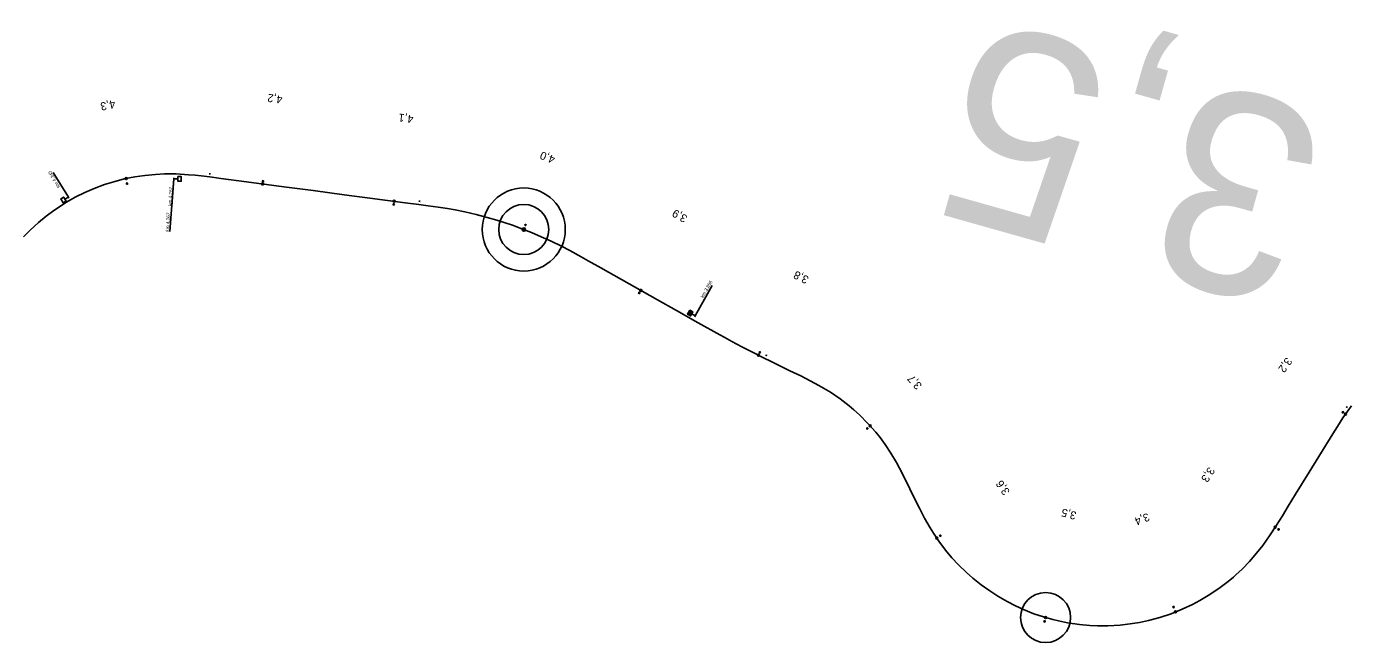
# Model space of a CAD drawing. Extents: x -738519 to -733269, y -1123734 to -1116309.
# Drawn here: x -737468 to -736475, y -1121770 to -1121307 of the extents above; entities that cross this region are included whole.
import ezdxf

# ---------------------------------------------------------------- set-up
doc = ezdxf.new("R2010")
doc.units = 0
doc.layers.add('Vrstva 1', color=7, linetype='Continuous')
doc.layers.add('Vrstva 7', color=7, linetype='Continuous')

msp = doc.modelspace()

# ---------------------------------------------------------------- linework, layer by layer
at = {"layer": 'Vrstva 1'}
for points in [[(-736980.55, -1121520.47), (-736994.79, -1121512.43), (-737006.13, -1121506.04), (-737037.15, -1121488.58), (-737041.66, -1121486.03), (-737045.03, -1121484.13), (-737051.95, -1121480.26), (-737060.41, -1121475.6), (-737066.65, -1121472.32), (-737074.48, -1121468.48), (-737081.82, -1121465.13), (-737089.05, -1121462.07), (-737096.43, -1121459.17), (-737103.49, -1121456.6), (-737109.72, -1121454.5), (-737115.02, -1121452.83), (-737122.31, -1121450.71), (-737130.59, -1121448.55), (-737139.15, -1121446.56), (-737146.38, -1121445.1), (-737152.14, -1121444.06), (-737159.1, -1121442.98), (-737166.62, -1121441.93), (-737173.49, -1121441.02), (-737183.78, -1121439.67), (-737210.21, -1121436.2), (-737229.58, -1121433.65), (-737252.71, -1121430.59), (-737274.7, -1121427.68), (-737302.82, -1121423.99), (-737322.07, -1121421.44), (-737328.44, -1121420.59), (-737334.37, -1121419.85), (-737341.18, -1121419.08), (-737346.17, -1121418.63), (-737355.36, -1121418.09), (-737364.19, -1121418.05), (-737371.06, -1121418.37), (-737378.94, -1121419.13), (-737386.42, -1121420.24), (-737394.37, -1121421.82), (-737402.27, -1121423.87), (-737409.27, -1121426.07), (-737416.85, -1121428.91), (-737423.86, -1121431.97), (-737430.65, -1121435.33), (-737438.05, -1121439.53), (-737442.95, -1121442.62), (-737447.09, -1121445.44), (-737453.01, -1121449.85), (-737458.73, -1121454.55), (-737464.94, -1121460.22), (-737469.92, -1121465.24)], [(-736980.55, -1121520.47), (-736994.79, -1121512.43), (-737006.13, -1121506.04), (-737037.15, -1121488.58), (-737041.66, -1121486.03), (-737045.03, -1121484.13), (-737051.95, -1121480.26), (-737060.41, -1121475.6), (-737066.65, -1121472.32), (-737074.48, -1121468.48), (-737081.82, -1121465.13), (-737089.05, -1121462.07), (-737096.43, -1121459.17), (-737103.49, -1121456.6), (-737109.72, -1121454.5), (-737115.02, -1121452.83), (-737122.31, -1121450.71), (-737130.59, -1121448.55), (-737139.15, -1121446.56), (-737146.38, -1121445.1), (-737152.14, -1121444.06), (-737159.1, -1121442.98), (-737166.62, -1121441.93), (-737173.49, -1121441.02), (-737183.78, -1121439.67), (-737210.21, -1121436.2), (-737229.58, -1121433.65), (-737252.71, -1121430.59), (-737274.7, -1121427.68), (-737302.82, -1121423.99), (-737322.07, -1121421.44), (-737328.44, -1121420.59), (-737334.37, -1121419.85), (-737341.18, -1121419.08), (-737346.17, -1121418.63), (-737355.36, -1121418.09), (-737364.19, -1121418.05), (-737371.06, -1121418.37), (-737378.94, -1121419.13), (-737386.42, -1121420.24), (-737394.37, -1121421.82), (-737402.27, -1121423.87), (-737409.27, -1121426.07), (-737416.85, -1121428.91), (-737423.86, -1121431.97), (-737430.65, -1121435.33), (-737438.05, -1121439.53), (-737442.95, -1121442.62), (-737447.09, -1121445.44), (-737453.01, -1121449.85), (-737458.73, -1121454.55), (-737464.94, -1121460.22), (-737469.92, -1121465.24)], [(-736474.59, -1121592.04), (-736481.1, -1121601.1), (-736485.16, -1121607.48), (-736488.53, -1121612.91), (-736506.33, -1121641.86), (-736516.48, -1121658.33), (-736522.03, -1121667.33), (-736526.39, -1121674.4), (-736530.86, -1121681.54), (-736535.51, -1121688.71), (-736538.31, -1121692.85), (-736541.08, -1121696.68), (-736545.71, -1121702.61), (-736550.96, -1121708.65), (-736556.62, -1121714.46), (-736561.26, -1121718.81), (-736563.11, -1121720.47), (-736566.92, -1121723.66), (-736574.05, -1121729.09), (-736581.91, -1121734.35), (-736588.31, -1121738.11), (-736593.86, -1121741.02), (-736601.6, -1121744.63), (-736609.85, -1121747.92), (-736618.18, -1121750.68), (-736626.81, -1121753), (-736633.46, -1121754.41), (-736638.73, -1121755.31), (-736647.92, -1121756.42), (-736657.2, -1121756.95), (-736665.04, -1121756.95), (-736670.71, -1121756.69), (-736678.37, -1121756.01), (-736687.55, -1121754.66), (-736694.14, -1121753.33), (-736698.54, -1121752.27), (-736705.39, -1121750.34), (-736712.58, -1121747.93), (-736720.34, -1121744.85), (-736726.52, -1121742.02), (-736732.78, -1121738.82), (-736739.75, -1121734.78), (-736746.5, -1121730.38), (-736752.15, -1121726.29), (-736758.31, -1121721.33), (-736763.2, -1121717.03), (-736769.17, -1121711.2), (-736774.04, -1121705.9), (-736778.8, -1121700.25), (-736783.92, -1121693.44), (-736787.95, -1121687.49), (-736790.42, -1121683.49), (-736794.6, -1121676.14), (-736798.44, -1121668.75), (-736802, -1121661.51), (-736805.53, -1121654.2), (-736809.5, -1121646.11), (-736813.27, -1121638.85), (-736815.64, -1121634.52), (-736819.82, -1121627.48), (-736824.16, -1121620.98), (-736827.96, -1121615.83), (-736831.21, -1121611.81), (-736836.97, -1121605.25), (-736843.45, -1121598.76), (-736847.46, -1121595.12), (-736851.06, -1121592.07), (-736857.9, -1121586.77), (-736865.18, -1121581.77), (-736873.79, -1121576.65), (-736880.36, -1121573.13), (-736887.36, -1121569.62), (-736895.48, -1121565.67), (-736909.09, -1121558.99), (-736915.79, -1121555.68), (-736924.59, -1121551.29), (-736931.47, -1121547.72), (-736939.01, -1121543.72), (-736944.31, -1121540.84), (-736948.04, -1121538.79), (-736964.17, -1121529.72), (-736980.55, -1121520.47)], [(-736474.59, -1121592.04), (-736481.1, -1121601.1), (-736485.16, -1121607.48), (-736488.53, -1121612.91), (-736506.33, -1121641.86), (-736516.48, -1121658.33), (-736522.03, -1121667.33), (-736526.39, -1121674.4), (-736530.86, -1121681.54), (-736535.51, -1121688.71), (-736538.31, -1121692.85), (-736541.08, -1121696.68), (-736545.71, -1121702.61), (-736550.96, -1121708.65), (-736556.62, -1121714.46), (-736561.26, -1121718.81), (-736563.11, -1121720.47), (-736566.92, -1121723.66), (-736574.05, -1121729.09), (-736581.91, -1121734.35), (-736588.31, -1121738.11), (-736593.86, -1121741.02), (-736601.6, -1121744.63), (-736609.85, -1121747.92), (-736618.18, -1121750.68), (-736626.81, -1121753), (-736633.46, -1121754.41), (-736638.73, -1121755.31), (-736647.92, -1121756.42), (-736657.2, -1121756.95), (-736665.04, -1121756.95), (-736670.71, -1121756.69), (-736678.37, -1121756.01), (-736687.55, -1121754.66), (-736694.14, -1121753.33), (-736698.54, -1121752.27), (-736705.39, -1121750.34), (-736712.58, -1121747.93), (-736720.34, -1121744.85), (-736726.52, -1121742.02), (-736732.78, -1121738.82), (-736739.75, -1121734.78), (-736746.5, -1121730.38), (-736752.15, -1121726.29), (-736758.31, -1121721.33), (-736763.2, -1121717.03), (-736769.17, -1121711.2), (-736774.04, -1121705.9), (-736778.8, -1121700.25), (-736783.92, -1121693.44), (-736787.95, -1121687.49), (-736790.42, -1121683.49), (-736794.6, -1121676.14), (-736798.44, -1121668.75), (-736802, -1121661.51), (-736805.53, -1121654.2), (-736809.5, -1121646.11), (-736813.27, -1121638.85), (-736815.64, -1121634.52), (-736819.82, -1121627.48), (-736824.16, -1121620.98), (-736827.96, -1121615.83), (-736831.21, -1121611.81), (-736836.97, -1121605.25), (-736843.45, -1121598.76), (-736847.46, -1121595.12), (-736851.06, -1121592.07), (-736857.9, -1121586.77), (-736865.18, -1121581.77), (-736873.79, -1121576.65), (-736880.36, -1121573.13), (-736887.36, -1121569.62), (-736895.48, -1121565.67), (-736909.09, -1121558.99), (-736915.79, -1121555.68), (-736924.59, -1121551.29), (-736931.47, -1121547.72), (-736939.01, -1121543.72), (-736944.31, -1121540.84), (-736948.04, -1121538.79), (-736964.17, -1121529.72), (-736980.55, -1121520.47)]]:
    msp.add_lwpolyline(points, dxfattribs=at)
at = {"layer": 'Vrstva 7'}
for p, q in [((-737436.24, -1121435.49), (-737447.53, -1121417.06)), ((-737436.24, -1121435.49), (-737447.53, -1121417.06)), ((-737357.17, -1121421.83), (-737360.13, -1121461.21)), ((-737357.17, -1121421.83), (-737358.7, -1121442.21)), ((-737357.17, -1121421.08), (-737357.17, -1121422.58)), ((-737357.17, -1121421.08), (-737357.17, -1121422.58)), ((-737329.7, -1121418.02), (-737330.69, -1121417.9)), ((-737329.7, -1121418.02), (-737330.69, -1121417.9)), ((-737330.26, -1121418.46), (-737330.13, -1121417.46)), ((-737330.26, -1121418.46), (-737330.13, -1121417.46)), ((-737290.32, -1121423.56), (-737290.42, -1121423.55)), ((-737290.32, -1121423.56), (-737290.42, -1121423.55)), ((-737435.87, -1121436.15), (-737436.61, -1121434.84)), ((-737435.87, -1121436.15), (-737436.61, -1121434.84)), ((-737392.17, -1121425.33), (-737392.27, -1121425.35)), ((-737392.17, -1121425.33), (-737392.27, -1121425.35)), ((-737192.31, -1121440.95), (-737192.41, -1121440.93)), ((-737192.31, -1121440.95), (-737192.41, -1121440.93)), ((-737172.62, -1121438.66), (-737173.61, -1121438.53)), ((-737172.62, -1121438.66), (-737173.61, -1121438.53)), ((-737173.18, -1121439.09), (-737173.05, -1121438.1)), ((-737173.18, -1121439.09), (-737173.05, -1121438.1)), ((-737093.59, -1121456.39), (-737093.69, -1121456.35)), ((-737093.59, -1121456.39), (-737093.69, -1121456.35)), ((-736966.49, -1121524.51), (-736953.84, -1121501.74)), ((-736966.49, -1121524.51), (-736953.84, -1121501.74)), ((-737008.34, -1121507.35), (-737008.43, -1121507.3)), ((-737008.34, -1121507.35), (-737008.43, -1121507.3)), ((-736969.72, -1121524.12), (-736971.65, -1121522.46)), ((-736969.72, -1121524.12), (-736971.65, -1121522.46)), ((-736971.16, -1121521.59), (-736969.22, -1121523.25)), ((-736971.16, -1121521.59), (-736969.22, -1121523.25)), ((-736968.73, -1121522.38), (-736970.66, -1121520.72)), ((-736968.73, -1121522.38), (-736970.66, -1121520.72)), ((-736966.86, -1121525.16), (-736966.12, -1121523.85)), ((-736966.86, -1121525.16), (-736966.12, -1121523.85)), ((-736917.97, -1121551.98), (-736918.06, -1121551.94)), ((-736917.97, -1121551.98), (-736918.06, -1121551.94)), ((-736912.72, -1121554.35), (-736913.62, -1121553.9)), ((-736912.72, -1121554.35), (-736913.62, -1121553.9)), ((-736913.39, -1121554.57), (-736912.95, -1121553.68)), ((-736913.39, -1121554.57), (-736912.95, -1121553.68)), ((-736477.64, -1121593.29), (-736478.45, -1121592.71)), ((-736477.64, -1121593.29), (-736478.45, -1121592.71)), ((-736477.76, -1121592.59), (-736478.34, -1121593.41)), ((-736477.76, -1121592.59), (-736478.34, -1121593.41)), ((-736480.98, -1121596.76), (-736481.04, -1121596.84)), ((-736480.98, -1121596.76), (-736481.04, -1121596.84)), ((-736837.53, -1121609.04), (-736837.59, -1121608.97)), ((-736837.53, -1121609.04), (-736837.59, -1121608.97)), ((-736782.72, -1121689.52), (-736782.79, -1121689.44)), ((-736782.72, -1121689.52), (-736782.79, -1121689.44)), ((-736529.22, -1121684.68), (-736529.27, -1121684.77)), ((-736529.22, -1121684.68), (-736529.27, -1121684.77)), ((-736607.91, -1121742.94), (-736608.01, -1121742.97)), ((-736607.91, -1121742.94), (-736608.01, -1121742.97)), ((-736704.59, -1121753.7), (-736704.69, -1121753.68)), ((-736704.59, -1121753.7), (-736704.69, -1121753.68))]:
    msp.add_line(p, q, dxfattribs=at)
for points in [[(-737357.17, -1121421.83), (-737354.17, -1121421.85), (-737354.18, -1121423.6), (-737351.68, -1121423.61), (-737351.66, -1121420.11), (-737354.16, -1121420.1), (-737354.17, -1121421.85)], [(-737357.17, -1121421.83), (-737354.17, -1121421.85), (-737354.18, -1121423.6), (-737351.68, -1121423.61), (-737351.66, -1121420.11), (-737354.16, -1121420.1), (-737354.17, -1121421.85)], [(-737436.24, -1121435.49), (-737438.85, -1121436.97), (-737439.72, -1121435.45), (-737441.89, -1121436.68), (-737440.17, -1121439.73), (-737437.99, -1121438.49), (-737438.85, -1121436.97)], [(-737436.24, -1121435.49), (-737438.85, -1121436.97), (-737439.72, -1121435.45), (-737441.89, -1121436.68), (-737440.17, -1121439.73), (-737437.99, -1121438.49), (-737438.85, -1121436.97)], [(-736966.49, -1121524.51), (-736969.1, -1121523.03), (-736968.24, -1121521.51), (-736970.42, -1121520.28), (-736972.14, -1121523.33), (-736969.96, -1121524.56), (-736969.1, -1121523.03)], [(-736966.49, -1121524.51), (-736969.1, -1121523.03), (-736968.24, -1121521.51), (-736970.42, -1121520.28), (-736972.14, -1121523.33), (-736969.96, -1121524.56), (-736969.1, -1121523.03)]]:
    msp.add_lwpolyline(points, dxfattribs=at)
for centre, radius in [((-737392.97, -1121421.54), 0.75), ((-737392.97, -1121421.54), 0.75), ((-737392.22, -1121425.34), 0.5), ((-737392.22, -1121425.34), 0.5), ((-737290.64, -1121425.59), 0.75), ((-737290.64, -1121425.59), 0.75), ((-737290.37, -1121423.56), 0.5), ((-737290.37, -1121423.56), 0.5), ((-737094.96, -1121459.75), 31.14), ((-737192.36, -1121440.94), 0.5), ((-737192.36, -1121440.94), 0.5), ((-737192.05, -1121438.58), 0.75), ((-737192.05, -1121438.58), 0.75), ((-737094.96, -1121459.75), 18.8), ((-737094.96, -1121459.75), 1.25), ((-737094.96, -1121459.75), 0.752), ((-737093.64, -1121456.37), 0.5), ((-737093.64, -1121456.37), 0.5), ((-737008.39, -1121507.32), 0.5), ((-737008.39, -1121507.32), 0.5), ((-737007.3, -1121505.38), 0.75), ((-737007.3, -1121505.38), 0.75), ((-736919.06, -1121554.05), 0.75), ((-736919.06, -1121554.05), 0.75), ((-736918.01, -1121551.96), 0.5), ((-736918.01, -1121551.96), 0.5), ((-736481.01, -1121596.8), 0.5), ((-736481.01, -1121596.8), 0.5), ((-736479.04, -1121598.23), 0.75), ((-736479.04, -1121598.23), 0.75), ((-736837.56, -1121609.01), 0.5), ((-736837.56, -1121609.01), 0.5), ((-736835.36, -1121607.08), 0.75), ((-736835.36, -1121607.08), 0.75), ((-736531.84, -1121683.05), 0.75), ((-736531.84, -1121683.05), 0.75), ((-736785.39, -1121691.26), 0.75), ((-736785.39, -1121691.26), 0.75), ((-736782.76, -1121689.48), 0.5), ((-736782.76, -1121689.48), 0.5), ((-736529.25, -1121684.73), 0.5), ((-736529.25, -1121684.73), 0.5), ((-736703.82, -1121750.78), 18.75), ((-736607.96, -1121742.95), 0.5), ((-736607.96, -1121742.95), 0.5), ((-736703.82, -1121750.78), 0.75), ((-736606.51, -1121746.59), 0.75), ((-736606.51, -1121746.59), 0.75), ((-736704.64, -1121753.69), 0.5), ((-736704.64, -1121753.69), 0.5)]:
    msp.add_circle(centre, radius, dxfattribs=at)

# ---------------------------------------------------------------- texts
for s, height, rotation, p in [('3,5', 150, 164.23929, (-736486.83, -1121375.92)), ('4,3', 6, 191.2392, (-737401.7, -1121362.58)), ('4,3', 6, 191.2392, (-737401.7, -1121362.58)), ('4,2', 6, 172.5266, (-737275.53, -1121359.44)), ('4,2', 6, 172.5266, (-737275.53, -1121359.44)), ('4,1', 6, 172.52041, (-737177.37, -1121374.19)), ('4,1', 6, 172.52041, (-737177.37, -1121374.19)), ('4,0', 6, 158.59692, (-737070.91, -1121404.97)), ('km 4,345', 2.5, 119.53683, (-737442.45, -1121427.73)), ('km 4,345', 2.5, 119.53683, (-737442.45, -1121427.73)), ('km 4,267', 2.5, 86.3475, (-737359.02, -1121442.04)), ('km 4,267', 2.5, 86.3475, (-737360.88, -1121461.37)), ('3,9', 6, 150.62787, (-736971.82, -1121449.75)), ('3,9', 6, 150.62787, (-736971.82, -1121449.75)), ('3,8', 6, 153.49486, (-736880.84, -1121495.46)), ('3,8', 6, 153.49486, (-736880.84, -1121495.46)), ('km 3,856', 2.5, 60.55098, (-736960.36, -1121511.27)), ('km 3,856', 2.5, 60.55098, (-736960.36, -1121511.27)), ('3,2', 6, 234.27545, (-736523.35, -1121555.17)), ('3,2', 6, 234.27545, (-736523.35, -1121555.17)), ('3,7', 6, 131.30697, (-736796.11, -1121576.55)), ('3,7', 6, 131.30697, (-736796.11, -1121576.55)), ('3,3', 6, 237.05141, (-736581.55, -1121637.37)), ('3,3', 6, 237.05141, (-736581.55, -1121637.37)), ('3,6', 6, 124.13192, (-736730.36, -1121656.36)), ('3,6', 6, 124.13192, (-736730.36, -1121656.36)), ('3,5', 6, 164.23929, (-736680.27, -1121671.84)), ('3,4', 6, 201.73795, (-736627.41, -1121672.21)), ('3,4', 6, 201.73795, (-736627.41, -1121672.21))]:
    msp.add_text(s, height=height, rotation=rotation, dxfattribs=at).set_placement(p)

doc.saveas('drawing.dxf')
